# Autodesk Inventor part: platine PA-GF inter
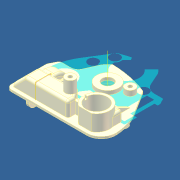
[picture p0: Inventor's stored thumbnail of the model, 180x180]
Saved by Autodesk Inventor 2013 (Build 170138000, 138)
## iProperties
Created: 2011-07
Part Number: platine PA-GF inter
Document SubType Name: Modeling
Designer: Laur
Density: 1.13 g/cm^3
Material: Nylon - 6/6
Mass: 2.66326 g
Surface Area: 28.7081 cm^2
Volume: 2.35687 cm^3
Author: Laur
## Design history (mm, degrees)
sketch "Esquisse1" dims "d572" = 1.2 (derived), "d605" = 4.5
  geometry: L1 (-32.1, 11.5)-(26.596, 11.5); L2 (26.596, 11.5)-(26.596, -43.876); L3 (26.596, -43.876)-(-32.1, -43.876); L4 (-32.1, -43.876)-(-32.1, 11.5); L5 (-26.823, -26.616)-(23.17, -27.471); L6 (-20.7, -5)-(-20.7, -19.1); L7 (12.39, -21.5)-(-18.3, -21.5); L8 (9.43, 5.794)-(15.506, -3.93); L9 (-20.482, -4.092)-(-19.208, -1.592); L10 (-13.9, -0.5)-(-17.426, -0.5); L11 (-9.341, 6.094)-(-11.616, 0.983); L12 (-6.696, 9.093)-(-8.758, 6.958); L13 (-20.1, -19.1)-(-20.1, -5); L14 (-19.947, -4.364)-(-18.674, -1.864); L15 (-17.426, -1.1)-(-13.9, -1.1); L16 (-11.068, 0.739)-(-8.793, 5.85); L17 (-8.326, 6.541)-(-6.447, 8.488); L18 (9.025, 5.31)-(14.997, -4.248); L19 (12.39, -20.9)-(-18.3, -20.9); C1 r 1.77 at (0, 0); C2 r 0.8 at (6.9, 2.25); C3 r 4.3 at (10.3, -14.8); C4 r 1.053 at (-10.659, -17.286); C5 r 2 at (0, -15.2); C6 r 2 at (6.9, 2.25); C7 r 0.8 at (0, -15.2); C8 r 1.77 at (-1.149, -7.006); A1 r 2.4 centre (-18.3, -19.1) between (-20.7, -19.1) and (-18.3, -21.5); A2 r 6.5 centre (12.39, -15) between (12.39, -21.5) and (18.882, -14.673); A3 r 22.4 centre (-3.49, -15.8) between (18.882, -14.673) and (15.506, -3.93); A4 r 2 centre (-18.7, -5) between (-20.482, -4.092) and (-20.7, -5); A5 r 2 centre (-17.426, -2.5) between (-17.426, -0.5) and (-19.208, -1.592); A6 r 2.5 centre (-13.9, 2) between (-13.9, -0.5) and (-11.616, 0.983); A7 r 3 centre (-6.6, 4.874) between (-8.758, 6.958) and (-9.341, 6.094); A8 r 45 centre (-7.5, -35.9) between (9.43, 5.794) and (-6.696, 9.093); A9 r 1.4 centre (-18.7, -5) between (-19.947, -4.364) and (-20.1, -5); A10 r 1.4 centre (-17.426, -2.5) between (-17.426, -1.1) and (-18.674, -1.864); A11 r 3.1 centre (-13.9, 2) between (-13.9, -1.1) and (-11.068, 0.739); A12 r 2.4 centre (-6.6, 4.874) between (-8.326, 6.541) and (-8.793, 5.85); A13 r 44.4 centre (-7.5, -35.9) between (9.025, 5.31) and (-6.447, 8.488); A14 r 21.8 centre (-3.49, -15.8) between (18.282, -14.703) and (14.997, -4.248); A15 r 5.9 centre (12.39, -15) between (12.39, -20.9) and (18.282, -14.703); A16 r 1.8 centre (-18.3, -19.1) between (-20.1, -19.1) and (-18.3, -20.9); 1 further point; 1 other entity
  constraints: 32 point on circle, 30 end point, 24 centre point, 13 tangent, 3 coincident, 2 parallel, 2 perpendicular, 1 horizontal, 1 vertical, 16 other
  dimensions: "d44" = 50 distance of L5.start L5.end; "d141" = 3.54 diameter of C1; "d142" = 4 diameter of C6; "d143" = 1.6 diameter of C2; "d144" = 4 diameter of C5 (= d142); "d145" = 1.6 diameter of C7 (= d143); "d150" = 2.4 radius of A1; "d176" = 2.25 vertical distance of C6.centre point (0, 0); "d181" = 21.5 distance from line of L7 point (0, 0); "d184" = 20.7 distance from line of point (0, 0) L6; "d205" = 13 diameter of A2; "d206" = 58 deg angle of L7 L8; "d210" = 6.9 horizontal distance of C2.centre point (0, 0); "d211" = 0 horizontal distance of C7.centre point (0, 0); "d212" = 15.2 distance of C7.centre point (0, 0); "d243" = 15.8 vertical distance of A3.centre point (0, 0); "d244" = 3.49 horizontal distance of point (0, 0) A3.centre; "d245" = 10.3 horizontal distance of C3.centre point (0, 0); "d246" = 14.8 vertical distance of point (0, 0) C3.centre; "d254" = 22.4 radius of A3; "d261" = 8.6 diameter of C3; "d268" = 27 deg angle of L6 L9; "d279" = 16.5 distance from line of L6.start L7; "d280" = 4 diameter of A4; "d281" = 21 distance between parallel lines of L10 L7; "d284" = 4 diameter of A5; "d302" = 114 deg angle of L10 L11; "d308" = 5 diameter of A6; "d309" = 6.8 distance from line of A6.centre L6; "d317" = 6 diameter of A7; "d320" = 6.6 horizontal distance of A7.centre point (0, 0); "d322" = 160 deg angle of L12 L11; "d326" = 90 diameter of A8; "d327" = 7.5 horizontal distance of A8.centre C1.centre; "d328" = 35.9 vertical distance of A8.centre C1.centre; "d335" = 0.6 distance between parallel lines of L6 L13; "d349" = 38.38239 distance from line of A14.start L13 (derived); "d388" = 3.54 diameter of C8; "d499" = 11.5 distance from line of L1 point (0, 0); "d500" = 32.1 distance from line of point (0, 0) L4; "d502" = 7.1 distance of C8.centre point (0, 0)
extrude "contour ext - ép 0,8" new body sketch "Esquisse1" distance "d336" = 0.8; taper "d337" = 0 deg
sketch "Esquisse2"
  geometry: L1 (20.1, -19.1)-(20.1, -5) reference; L2 (19.947, -4.364)-(18.674, -1.864) reference; L3 (17.426, -1.1)-(13.9, -1.1) reference; L4 (11.068, 0.739)-(8.793, 5.85) reference; L5 (8.326, 6.541)-(6.447, 8.488) reference; L6 (-9.025, 5.31)-(-14.997, -4.248) reference; L7 (-12.39, -20.9)-(18.3, -20.9) reference; L8 (-13.81, -4.99)-(-8.082, 4.177); L9 (5.87, 7.069)-(7.319, 5.568); L10 (7.514, 5.281)-(9.789, 0.17); L11 (13.9, -2.5)-(17.426, -2.5); L12 (17.426, -2.5)-(18.7, -5); L13 (18.7, -5)-(18.7, -19.1); L14 (18.3, -19.5)-(-12.39, -19.5); C1 r 4.3 at (-10.3, -14.8) reference; C2 r 2 at (-6.9, 2.25) reference; C3 r 2 at (0, -15.2) reference; C4 r 1.77 at (0, 0) reference; C5 r 1.053 at (10.659, -17.286) reference; A1 r 1.4 centre (18.7, -5) between (20.1, -5) and (19.947, -4.364) reference; A2 r 1.4 centre (17.426, -2.5) between (18.674, -1.864) and (17.426, -1.1) reference; A3 r 3.1 centre (13.9, 2) between (11.068, 0.739) and (13.9, -1.1) reference; A4 r 2.4 centre (6.6, 4.874) between (8.793, 5.85) and (8.326, 6.541) reference; A5 r 44.4 centre (7.5, -35.9) between (6.447, 8.488) and (-9.025, 5.31) reference; A6 r 21.8 centre (3.49, -15.8) between (-14.997, -4.248) and (-18.282, -14.703) reference; A7 r 5.9 centre (-12.39, -15) between (-18.282, -14.703) and (-12.39, -20.9) reference; A8 r 1.8 centre (18.3, -19.1) between (18.3, -20.9) and (20.1, -19.1) reference; A9 r 43 centre (7.5, -35.9) between (5.87, 7.069) and (-8.082, 4.177); A10 r 1 centre (6.6, 4.874) between (7.514, 5.281) and (7.319, 5.568); A11 r 4.5 centre (13.9, 2) between (9.789, 0.17) and (13.9, -2.5); A12 r 0 centre (17.426, -2.5) between (17.426, -2.5) and (17.426, -2.5); A13 r 0 centre (18.7, -5) between (18.7, -5) and (18.7, -5); A14 r 0.4 centre (18.3, -19.1) between (18.3, -19.5) and (18.7, -19.1); A15 r 4.5 centre (-12.39, -15) between (-16.884, -14.774) and (-12.39, -19.5); A16 r 20.4 centre (3.49, -15.8) between (-13.81, -4.99) and (-16.884, -14.774); 2 further points
  constraints: 14 end point, 12 point on circle, 8 centre point, 4 coincident with centre, 14 other
  dimensions: "d518" = 1.4 distance between parallel lines of L1 L13
extrude "centrage int - ép 0,8" join sketch "Esquisse2" distance "d339" = 0.8; taper "d340" = 0 deg
sketch "Esquisse3"
  geometry: C1 r 2 at (6.9, 2.25) reference; C2 r 0.8 at (6.9, 2.25)
  constraints: 1 centre point, 1 coincident
  dimensions: "d341" = 1.6 diameter of C2
extrude "bossage1 fix capot" join sketch "Esquisse3" stored distance "d342" = 5.8; taper "d343" = 0 deg
sketch "Esquisse4"
  geometry: C1 r 2 at (0, 0) reference; C2 r 0.8 at (0, 0)
  constraints: 1 centre point, 1 coincident
  dimensions: "d344" = 1.6 diameter of C2
extrude "alésage1 pour vis fix capot" cut sketch "Esquisse4" distance "d345" = 5; taper "d346" = 0 deg
sketch "Esquisse5"
  geometry: L1 (13.81, -4.99)-(8.082, 4.177) reference; L2 (-5.87, 7.069)-(-7.319, 5.568) reference; L3 (-7.514, 5.281)-(-9.789, 0.17) reference; L4 (-13.9, -2.5)-(-17.426, -2.5) reference; L5 (-17.426, -2.5)-(-18.7, -5) reference; L6 (-18.7, -5)-(-18.7, -19.1) reference; L7 (-18.3, -19.5)-(12.39, -19.5) reference; L8 (3.4, -19.5)-(-18.7, -19.5); L9 (-18.7, -19.5)-(-18.7, -13.2); L10 (-18.7, -13.2)-(1.041, -13.2); L11 (3.4, -16.569)-(3.4, -19.5); L12 (1.041, -13.2)-(3.4, -16.569); C1 r 2 at (0, -15.2) reference; A1 r 43 centre (-7.5, -35.9) between (8.082, 4.177) and (-5.87, 7.069) reference; A2 r 1 centre (-6.6, 4.874) between (-7.319, 5.568) and (-7.514, 5.281) reference; A3 r 4.5 centre (-13.9, 2) between (-13.9, -2.5) and (-9.789, 0.17) reference; A4 r 0.4 centre (-18.3, -19.1) between (-18.7, -19.1) and (-18.3, -19.5) reference; A5 r 4.5 centre (12.39, -15) between (12.39, -19.5) and (16.884, -14.774) reference; A6 r 20.4 centre (-3.49, -15.8) between (16.884, -14.774) and (13.81, -4.99) reference
  constraints: 10 end point, 2 parallel, 2 point on line, 2 tangent, 1 horizontal, 1 perpendicular
  dimensions: "d521" = 55 deg angle of L10 L12; "d522" = 22.1 distance between parallel lines of L11 L6
extrude "bossage loge carte" join sketch "Esquisse5" distance "d523" = 6; taper "d524" = 0 deg
sketch "Esquisse6"
  geometry: C1 r 2 at (0, -15.2); A1 r 2 centre (0, -15.2) between (0, -13.2) and (1.638, -14.053) reference
  constraints: 1 centre point, 1 coincident, 1 concentric
extrude "bossage2 fix capot" join sketch "Esquisse6" distance "d525" = 4.8; taper "d526" = 0 deg
sketch "Esquisse7"
  geometry: C1 r 2 at (0, -15.2) reference; C2 r 0.8 at (0, -15.2)
  constraints: 1 centre point, 1 coincident
  dimensions: "d530" = 1.6 diameter of C2
extrude "alésage2 pour vis fix capot" cut sketch "Esquisse7" distance "d528" = 5; taper "d529" = 0 deg
sketch "Esquisse8"
  geometry: L1 (1.041, -13.2)-(1.638, -14.053); L2 (1.638, -14.053)-(3.4, -16.569); L3 (-17.426, -1.1)-(-13.9, -1.1); L4 (15.45, -13.351)-(15.45, -9.25); L5 (15.45, -9.25)-(9.549, -9.25); L6 (9.549, -9.25)-(1.041, -13.2); L7 (7.744, -19.5)-(12.856, -19.5); L8 (3.4, -19.5)-(-18.3, -19.5); L9 (3.4, -16.569)-(5.251, -16.569); L10 (3.4, -19.5)-(-18.7, -19.5) reference; C1 r 4.3 at (10.3, -14.8); C2 r 4.3 at (10.3, -14.8) reference; A1 r 5.35 centre (10.3, -14.8) between (12.856, -19.5) and (7.744, -19.5)
  constraints: 18 end point, 4 point on circle, 2 centre point, 2 coincident, 2 collinear, 2 parallel, 2 perpendicular, 1 tangent
  dimensions: "d531" = 10.7 diameter of A1; "d533" = 5.55 distance from line of L5 C1.centre; "d534" = 5.15 distance from line of L4 C1.centre
extrude "bossage connect ph1" join sketch "Esquisse8" distance "d535" = 2.3; taper "d536" = 0 deg
sketch "Esquisse9"
  geometry: L1 (15.45, -9.25)-(15.45, -13.351) reference; L2 (9.549, -9.25)-(15.45, -9.25) reference; L3 (1.041, -13.2)-(9.549, -9.25) reference; L4 (5.251, -16.569)-(3.4, -16.569) reference; L5 (12.856, -19.5)-(7.744, -19.5) reference; C1 r 4.3 at (10.3, -14.8) reference; A1 r 5.35 centre (10.3, -14.8) between (12.856, -19.5) and (15.45, -13.351) reference; A2 r 5.35 centre (10.3, -14.8) between (5.251, -16.569) and (7.744, -19.5) reference; A3 r 5.35 centre (10.3, -14.8) between (8.047, -9.947) and (5.251, -16.569)
  constraints: 3 point on circle, 2 point on line, 1 centre point, 1 coincident, 1 end point
extrude "bossage connect ph2" join sketch "Esquisse9" distance "d537" = 1.8; taper "d538" = 0 deg
sketch "Esquisse10"
  geometry: L1 (12.856, -19.5)-(7.744, -19.5) reference; L2 (15.45, -9.25)-(15.45, -13.351) reference; L3 (9.549, -9.25)-(15.45, -9.25) reference; L4 (8.047, -9.947)-(9.549, -9.25) reference; C1 r 4.3 at (10.3, -14.8) reference; A1 r 5.35 centre (10.3, -14.8) between (12.856, -19.5) and (15.45, -13.351) reference; A2 r 5.35 centre (10.3, -14.8) between (8.047, -9.947) and (7.744, -19.5) reference; A3 r 5.35 centre (10.3, -14.8) between (15.45, -13.351) and (8.047, -9.947)
  constraints: 2 end point, 2 point on circle, 1 centre point, 1 coincident, 1 concentric, 1 point on line
extrude "bossage connect ph3" join sketch "Esquisse10" distance "d539" = 2.4; taper "d540" = 0 deg
sketch "Esquisse12"
  geometry: L1 (3.4, -16.569)-(1.041, -13.2) reference; L2 (5.251, -16.569)-(3.4, -16.569) reference; L3 (2.7, -15.569)-(5.006, -15.569); A1 r 5.35 centre (10.3, -14.8) between (8.047, -9.947) and (5.251, -16.569) reference
  constraints: 2 end point, 1 parallel, 1 point on circle, 1 point on line
  dimensions: "d541" = 1 distance between parallel lines of L2 L3
extrude "nervure connect à  loge carte" join sketch "Esquisse12" distance "d542" = 2.4; taper "d543" = 0 deg
node "Plan de construction1"
sketch "Esquisse14"
  geometry: L1 (1.6, 2.851)-(1.6, -5.749) reference; L2 (0, 0)-(-4.1, 0) reference; L3 (0, 4.101)-(0, 0) reference; L4 (0, 4.101)-(-4.1, 4.101) reference; L5 (-4.1, 4.101)-(-4.1, 0) reference; L6 (-3, 4.101)-(0, 10.101); L7 (0, -1.352)-(0, 9.103) reference; L8 (0, 18.661)-(0, 9.103) reference
  constraints: 2 end point, 2 point on line
  dimensions: "d548" = 6 distance from line of L6.end L4; "d549" = 3 distance from line of L6.start L7
feature "Nervure connect à platine" sketch "Esquisse14" dims "d550" = 1, "d551" = 1, "d552" = 0
node "Plan de construction bossage lat"
sketch "Esquisse16"
  geometry: L1 (0, 0.4)-(0, 14.5); L2 (2.5, 5.9)-(2.5, 10.4); L3 (0, 15.136)-(0, 14.5); L4 (0, 15.136)-(0, 17.636); L5 (0, 6)-(0, 15.273); A1 r 6 centre (-3.5, 10.4) between (2.5, 10.4) and (0, 15.273); 2 further points; 1 other entity
  constraints: 10 end point, 2 point on circle, 1 centre point, 1 parallel, 1 point on line, 1 tangent, 4 other
  dimensions: "d554" = 12 diameter of A1; "d555" = 4.5 dimension on A1.centre; "d556" = 2.5 distance between parallel lines of L2 L1
extrude "bossage latéral loge carte" join sketch "Esquisse16" stored distance "d557" = 5.3; taper "d558" = 0 deg
sketch "Esquisse20"
  geometry: L1 (2.5, 6.3)-(2.5, 10.4) reference; L2 (1.3, 3.323)-(1.3, 10.2); L3 (-1.6, 14.5)-(-1.6, 0.4) reference; L4 (1.3, 3.323)-(-1.6, 3.323); L5 (-1.6, 14.5)-(-1.6, 14.812); A1 r 6 centre (-3.5, 10.4) between (2.5, 10.4) and (0, 15.273) reference; A2 r 4.804 centre (-3.5, 10.4) between (1.3, 10.2) and (-1.6, 14.812)
  constraints: 6 end point, 2 perpendicular, 2 point on circle, 1 centre point, 1 point on line
  dimensions: "d564" = 1.2 distance between parallel lines of L2 L1
extrude "évidemment bossage lat" cut sketch "Esquisse20" stored distance "d565" = 2.9; taper "d566" = 0 deg
sketch "Esquisse22"
  geometry: 2 further points
  constraints: 1 other
extrude "Extrusion17" join sketch "Esquisse22" stored distance "d574" = 6; taper "d575" = 0 deg
sketch "Esquisse21"
  geometry: L1 (18.7, -13.2)-(0, -13.2) reference; L2 (-3.4, -16.569)-(-3.4, -19.5) reference; L3 (-1.638, -14.053)-(-3.4, -16.569) reference; L4 (-1.041, -13.2)-(-1.638, -14.053) reference; L5 (0, -13.2)-(-1.041, -13.2) reference; L6 (18.3, -19.5)-(-12.39, -19.5) reference; L7 (-2.2, -18.3)-(17.5, -18.3); L8 (17.5, -18.3)-(17.5, -14.4); L9 (17.5, -14.4)-(-0.416, -14.4); L10 (-0.416, -14.4)-(-2.2, -16.947); L11 (-2.2, -16.947)-(-2.2, -18.3); L12 (18.7, -19.5)-(18.7, -13.2) reference; L13 (-3.4, -19.5)-(18.7, -19.5) reference; C1 r 2 at (0, -15.2) reference; A1 r 2 centre (0, -15.2) between (-1.638, -14.053) and (0, -13.2) reference; A2 r 2 centre (0, -15.2) between (0, -13.2) and (-1.638, -14.053) reference
  constraints: 10 end point, 4 parallel, 1 perpendicular
  dimensions: "d569" = 1.2 distance between parallel lines of L7 L6; "d570" = 1.2 distance between parallel lines of L2 L11 (derived); "d571" = 1.2 distance between parallel lines of L3 L10 (derived); "d572" = 1.2 distance between parallel lines of L1 L9 (derived)
extrude "forme1 logement pcb" cut sketch "Esquisse21" distance "d567" = 6.4; taper "d568" = 0 deg
sketch "Esquisse23"
  geometry: L1 (0, 6)-(0, 0) reference; L2 (0, 0)-(18.7, 0) reference; L3 (4.5, 0)-(0, 4.5)
  constraints: 2 end point, 2 point on line
  dimensions: "d576" = 4.5 distance from line of L1 L3.start; "d577" = 4.5 distance from line of L3.end L2
extrude "forme2 logement pcb" cut sketch "Esquisse23" stored distance "d578" = 6; taper "d579" = 0 deg
sketch "Esquisse24"
  geometry: L1 (-2.35, 6.4)-(-4.45, 4.3) reference; L2 (-4.45, 0)-(-4.45, 4.3) reference; L3 (-2.35, 6.4)-(13.466, 6.4) reference; L4 (-0.653, 6.4)-(-4.45, 2.603)
  constraints: 2 end point, 2 point on line, 1 parallel
  dimensions: "d580" = 1.2 distance between parallel lines of L1 L4
extrude "forme3 logement pcb" join sketch "Esquisse24" stored distance "d581" = 6; taper "d582" = 0 deg
fillet "arrondis platine" dims "d583" = 1
node "Axe de construction1"
sketch "Esquisse25"
  geometry: L1 (6.029, -15.3)-(4.95, -15.3); L2 (4.95, -15.3)-(4.95, -14.3); L3 (4.95, -14.3)-(6.029, -14.3); L4 (6.029, -14.3)-(6.029, -15.3); A1 r 4.3 centre (10.3, -14.8) between (6.029, -14.3) and (6.029, -15.3) reference; A2 r 5.35 centre (10.3, -14.8) between (12.856, -19.5) and (7.744, -19.5) reference
  constraints: 8 end point, 2 parallel, 2 point on circle, 1 horizontal, 1 perpendicular, 1 tangent
  dimensions: "d586" = 1 distance between parallel lines of L1 L3
extrude "évidemment pour ergot connecteur" cut sketch "Esquisse25" distance "d587" = 1; taper "d588" = 0 deg
sketch "Esquisse26"
  geometry: L1 (-0.416, -14.4)-(17.5, -14.4) reference; L2 (18.7, -5)-(18.7, -19.1) reference; L3 (18.7, -14.4)-(17.4, -14.4); L4 (17.4, -14.4)-(17.4, -6); L5 (17.4, -6)-(18.7, -6); L6 (18.7, -6)-(18.7, -14.4); 1 further point
  constraints: 8 end point, 2 parallel, 1 collinear, 1 horizontal, 1 perpendicular, 1 point on line
  dimensions: "d589" = 8.4 distance between parallel lines of L3 L5; "d590" = 1.3 distance between parallel lines of L6 L4
extrude "forme logement butée axiale" join sketch "Esquisse26" distance "d591" = 8.5; taper "d592" = 0 deg
fillet "arrondi forme logement butée axiale" dims "d593" = 2
sketch "Esquisse27"
  geometry: L1 (-0.8, 4.7)-(-7.3, 4.7) reference; L2 (-0.8, 4.7)-(-0.8, 0) reference; L3 (-7.9, 6.35)-(-2.8, 6.35); L4 (-2.8, 6.35)-(-2.8, 11.45); L5 (-2.8, 11.45)-(-7.9, 11.45); L6 (-7.9, 11.45)-(-7.9, 6.35); 1 further point
  constraints: 8 end point, 2 parallel, 1 horizontal, 1 perpendicular
  dimensions: "d594" = 5.1 distance between parallel lines of L5 L3; "d595" = 5.1 distance between parallel lines of L4 L6; "d596" = 1.65 distance between parallel lines of L1 L3; "d597" = 2 distance between parallel lines of L2 L4
extrude "logement butée axiale" cut sketch "Esquisse27" distance "d598" = 1; taper "d599" = 0 deg
sketch "Esquisse28"
  geometry: L1 (18.7, -12.4)-(17.4, -12.4) reference; L2 (17.4, -12.4)-(17.4, -8) reference; L3 (17.4, -11.85)-(17.9, -11.85); L4 (17.9, -11.85)-(17.9, -8.55); L5 (17.9, -8.55)-(17.4, -8.55); L6 (17.4, -8.55)-(17.4, -11.85)
  constraints: 8 end point, 2 parallel, 1 horizontal, 1 perpendicular, 1 point on line
  dimensions: "d600" = 3.3 distance between parallel lines of L5 L3; "d601" = 0.55 distance between parallel lines of L1 L3; "d602" = 0.5 distance between parallel lines of L2 L4
extrude "evidemment1 pour extrémité arbre vis" cut sketch "Esquisse28" distance "d603" = 4.5; taper "d604" = 0 deg
sketch "Esquisse29"
  geometry: L1 (-4.8, 10.55)-(-4.8, 7.25) reference; L2 (-4.8, 7.25)-(-7.9, 7.25) reference; A1 r 1.65 centre (-4.8, 8.9) between (-4.8, 7.25) and (-4.8, 10.55)
  constraints: 2 end point, 2 point on circle, 1 centre point, 1 midpoint
extrude "evidemment2 pour extrémité arbre vis" cut sketch "Esquisse29" stored distance "d605" = 4.5; taper "d606" = 0 deg
sketch "Esquisse30"
  geometry: L1 (15.95, -14.4)-(17.4, -14.4) reference; L2 (10.69, -3.7)-(-9.81, -3.7); C1 r 1.7 at (10.69, -3.7) reference; C2 r 1.7 at (10.69, -3.7) reference; C3 r 1 at (-9.81, -3.7) reference; C4 r 1 at (10.69, -3.7) reference; C5 r 0.665 at (10.69, -3.7); C6 r 0.665 at (-9.81, -3.7); C7 r 1.77 at (0, 0) reference; A1 r 2 centre (10.69, -3.7) between (11.19, -5.636) and (8.798, -3.051) reference; A2 r 1.7 centre (-9.81, -3.7) between (-8.443, -2.689) and (-8.112, -3.616) reference; A3 r 1.7 centre (-9.81, -3.7) between (-8.443, -2.689) and (-8.112, -3.616) reference; A4 r 1.7 centre (-9.81, -3.7) between (-8.443, -2.689) and (-8.112, -3.616) reference; A5 r 1.7 centre (-9.81, -3.7) between (-8.443, -2.689) and (-8.112, -3.616) reference; A6 r 2 centre (-9.81, -3.7) between (-8.47, -2.216) and (-11.461, -2.571) reference; 1 further point
  constraints: 5 coincident, 2 centre point, 2 end point, 1 parallel, 9 other
  dimensions: "d616" = 1.33 diameter of C5; "d617" = 1.33 diameter of C6 (derived); "d672" = 3.7 distance from line of L2 C7.centre (derived)
  node "Référence1"
  node "Référence2"
  node "Référence3"
  node "Référence4"
  node "Référence5"
  node "Référence6"
  node "Référence7"
  node "Référence8"
  node "Référence9"
  node "Référence10"
node "Plan de construction4"
extrude "piliers cage" join sketch "Esquisse30" stored distance "d618" = 4.5; taper "d619" = 0 deg
sketch "Esquisse31"
  geometry: C1 r 2 at (0, 0) reference; C2 r 2 at (-20.5, 0) reference; C3 r 1.7 at (0, 0) reference; A1 r 1.7 centre (-20.5, 0) between (-19.133, 1.011) and (-18.802, 0.084) reference; 1 further point
  constraints: 1 coincident, 3 other
extrude "centrages cage" join sketch "Esquisse31" distance "d620" = 1; taper "d621" = 0 deg
sketch "Esquisse32"
  geometry: C1 r 1.77 at (0, 0) reference; C2 r 2 at (-6.9, 2.25) reference; C3 r 3.75 at (0, 0); A1 r 5.25 centre (0, 0) between (-5.236, 0.384) and (-4.456, 2.776); A2 r 2.5 centre (-6.9, 2.25) between (-4.456, 2.776) and (-5.236, 0.384)
  constraints: 4 point on circle, 3 centre point, 3 coincident
  dimensions: "d624" = 10.5 diameter of A1; "d625" = 7.5 diameter of C3; "d626" = 5 diameter of A2
extrude "bossage pour palier" join sketch "Esquisse32" distance "d627" = 2.5; taper "d628" = 0 deg
sketch "Esquisse33"
  geometry: C1 r 1.77 at (0, 0) reference; C2 r 4.5 at (0, 0); C3 r 2.25 at (0, 0)
  constraints: 2 centre point, 2 coincident
  dimensions: "d629" = 9 diameter of C2; "d630" = 4.5 diameter of C3
extrude "bossage pour joint" join sketch "Esquisse33" distance "d631" = 1.5; taper "d632" = 0 deg
sketch "Esquisse34"
  geometry: C1 r 2.25 at (0, 0) reference
extrude "passage arbre de sortie" cut sketch "Esquisse34" stored distance "d633" = 5; taper "d634" = 0 deg
sketch "Esquisse35"
  geometry: C1 r 2.25 at (0, 0) reference; C2 r 3.75 at (0, 0) reference; C3 r 3.4 at (0, 0)
  constraints: 1 centre point, 1 coincident
  dimensions: "d635" = 6.8 diameter of C3
extrude "logement joint torique" cut sketch "Esquisse35" distance "d636" = 2; taper "d637" = 0 deg
node "Plan de construction nervure 2"
sketch "Esquisse36"
  geometry: L1 (4.8, 1.2)-(4.8, 5.1) reference; L2 (4.8, 5.1)-(-1.6, 5.1) reference; L3 (-1.6, 5.1)-(-1.6, 14.062) reference; L4 (-1.6, 14.062)-(-7.05, 14.062) reference; L5 (-7.05, 14.062)-(-7.05, 14.418) reference; L6 (-7.05, 14.418)-(-6.05, 14.418) reference; L7 (-6.05, 14.418)-(-6.05, 17.182) reference; L8 (-6.05, 17.182)-(-7.05, 17.182) reference; L9 (-7.05, 17.182)-(-7.05, 17.538) reference; L10 (-7.05, 17.538)-(-1.6, 17.538) reference; L11 (-1.6, 17.538)-(-1.6, 19.87) reference; L12 (-1.6, 19.87)-(-0.8, 19.87) reference; L13 (-0.8, 19.87)-(-0.8, 23.312) reference; L14 (-0.8, 23.312)-(0, 23.312) reference; L15 (0, 23.312)-(0, 6.3) reference; L16 (0, 6.3)-(5, 6.3) reference; L17 (6, 5.3)-(6, 1) reference; L18 (5, 0)-(0, 0) reference; L19 (0, 0)-(0, -1.4) reference; L20 (0, -1.4)-(-0.8, -1.4) reference; L21 (-0.8, -1.4)-(-0.8, 0) reference; L22 (-0.8, 0)-(-1.6, 0) reference; L23 (-1.6, 0)-(-1.6, 1.2) reference; L24 (-1.6, 1.2)-(4.8, 1.2) reference; L25 (4, 6.3)-(0, 13.3); L26 (0, 13.3)-(0, 6.3); L27 (0, 6.3)-(4, 6.3); L28 (4, 6.3)-(0, 13.3); L29 (0, 13.3)-(0, 6.3); L30 (4, 6.3)-(0, 6.3); A1 r 1 centre (5, 5.3) between (6, 5.3) and (5, 6.3) reference; A2 r 1 centre (5, 1) between (5, 0) and (6, 1) reference
  constraints: 12 end point, 5 collinear, 2 point on line
  dimensions: "d638" = 7 distance from line of L25.end L16; "d639" = 4 distance from line of L15 L25.start
feature "Nervure2 logement pcb" sketch "Esquisse36" dims "d640" = 1, "d641" = 1.1, "d642" = 0
node "Plan de construction nervure 3"
sketch "Esquisse37"
  geometry: L1 (-1.3, -1.931)-(-1.3, 2.369) reference; L2 (-0.3, 3.369)-(4.7, 3.369) reference; L3 (4.7, 18.424)-(4.7, 24.938) reference; L4 (4.7, 24.938)-(5.5, 24.938) reference; L5 (5.5, 24.938)-(5.5, 23.534) reference; L6 (6.3, 13.29)-(6.3, 2.169) reference; L7 (6.3, 2.169)-(-0.1, 2.169) reference; L8 (-0.1, 2.169)-(-0.1, -1.731) reference; L9 (-0.1, -1.731)-(6.3, -1.731) reference; L10 (6.3, -1.731)-(6.3, -2.931) reference; L11 (6.3, -2.931)-(5.5, -2.931) reference; L12 (5.5, -2.931)-(5.5, -4.331) reference; L13 (5.5, -4.331)-(4.7, -4.331) reference; L14 (4.7, -4.331)-(4.7, -2.931) reference; L15 (4.7, -2.931)-(-0.3, -2.931) reference; L16 (1.2, 3.369)-(4.7, 7.369); L17 (5.5, 23.534)-(6.3, 23.534) reference; L18 (6.3, 23.534)-(6.3, 19.848) reference; L19 (6.3, 19.848)-(8.8, 19.848) reference; L20 (8.8, 19.848)-(8.8, 13.29) reference; L21 (8.8, 13.29)-(6.3, 13.29) reference; L22 (4.7, 3.369)-(4.7, 14.714) reference; L23 (4.7, 14.714)-(3.2, 14.714) reference; L24 (3.2, 14.714)-(3.2, 18.424) reference; L25 (3.2, 18.424)-(4.7, 18.424) reference; A1 r 1 centre (-0.3, 2.369) between (-0.3, 3.369) and (-1.3, 2.369) reference; A2 r 1 centre (-0.3, -1.931) between (-1.3, -1.931) and (-0.3, -2.931) reference
  constraints: 2 end point, 2 point on line
  dimensions: "d644" = 3.5 distance from line of L3 L16.start; "d645" = 4 distance from line of L2 L16.end
feature "Nervure3 logement pcb" sketch "Esquisse37" dims "d646" = 1, "d647" = 1.1, "d648" = 0
sketch "Esquisse38"
  geometry: L1 (3.354, 4.039)-(6.07, 6.862); L2 (-2.711, 4.496)-(-3.43, 5.688); L3 (4.524, 6.4)-(-2, 5.4); L4 (-2, 5.4)-(-2.094, 6.016); L5 (-0.893, 5.57)-(-0.998, 6.252); L6 (0.204, 5.738)-(0.094, 6.457); L7 (2.122, 6.032)-(2.012, 6.748); L8 (4.524, 6.4)-(4.433, 6.991); L9 (3.219, 6.2)-(3.115, 6.876); L10 (5.87, 7.069)-(7.319, 5.568) reference; L11 (0, 0)-(-3.43, 5.688); L12 (0, 0)-(-3.43, 5.688); A1 r 5.25 centre (0, 0) between (-5.236, 0.384) and (-4.456, 2.776) reference; 2 further points
  constraints: 22 end point, 5 parallel, 5 point on line, 2 collinear, 2 point on circle, 1 perpendicular, 8 other
  dimensions: "d651" = 2.71108 horizontal distance of L11.start L2.start; "d652" = 3.35397 horizontal distance of L11.start L1.start; "d653" = 6.6 distance of L3.start L3.end; "d654" = 2 horizontal distance of L3.end L11.start; "d655" = 5.4 vertical distance of L3.end L11.start; "d656" = 6.4 vertical distance of L11.start L3.start; "d657" = 1.11991 distance between parallel lines of L4 L5; "d658" = 1.11 distance between parallel lines of L7 L9; "d659" = 1.32 distance between parallel lines of L8 L9; "d660" = 1.94 distance between parallel lines of L6 L7; "d661" = 1.11009 distance between parallel lines of L5 L6 (derived); "d664" = 9.5 horizontal distance of L1.end L2.end
extrude "languette de butée roue de sortie" join sketch "Esquisse38" distance "d662" = 6; taper "d663" = 0 deg
sketch "Esquisse39"
  geometry: A1 r 2 centre (0, 0) between (1.998, -0.094) and (1.438, 1.39) reference; A2 r 5.25 centre (9.81, 3.7) between (7.099, 8.196) and (5.354, 6.476) reference; A3 r 8.685 centre (9.81, 3.7) between (1.438, 1.39) and (1.998, -0.094)
  constraints: 4 point on circle, 1 centre point, 1 coincident
  dimensions: "d666" = 0.2 dimension on A1 A3
extrude "correction pilier cage pour roue de sortie" cut sketch "Esquisse39" stored distance "d667" = 10; taper "d668" = 0 deg
node "Solide1"
node "Corps solides"
node "Corps surfaciques"
node "Image1"
node "Boucle projetée1"
node "Boucle projetée2"
node "Boucle projetée3"
node "Boucle projetée4"
node "Boucle projetée13"
node "Boucle projetée14"
node "Référence11"
node "Référence12"
node "Projeter les arêtes coupées1"
node "Projeter les arêtes coupées2"
other parameters: "d229" = 45, "d547" = -3.65, "d614" = -4.2, "d615" = -9, "d643" = -7.5
